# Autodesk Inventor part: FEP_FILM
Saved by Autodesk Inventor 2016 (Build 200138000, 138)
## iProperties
Created: 2016-03
Part Number: FEP_FILM
Material: Generic
Document SubType Name: Modeling
Designer: bongo_000
Density: 1 g/cm^3
Appearance: Default
Author: bongo_000
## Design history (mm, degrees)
feature "SOLID1"
body "Solid1"
